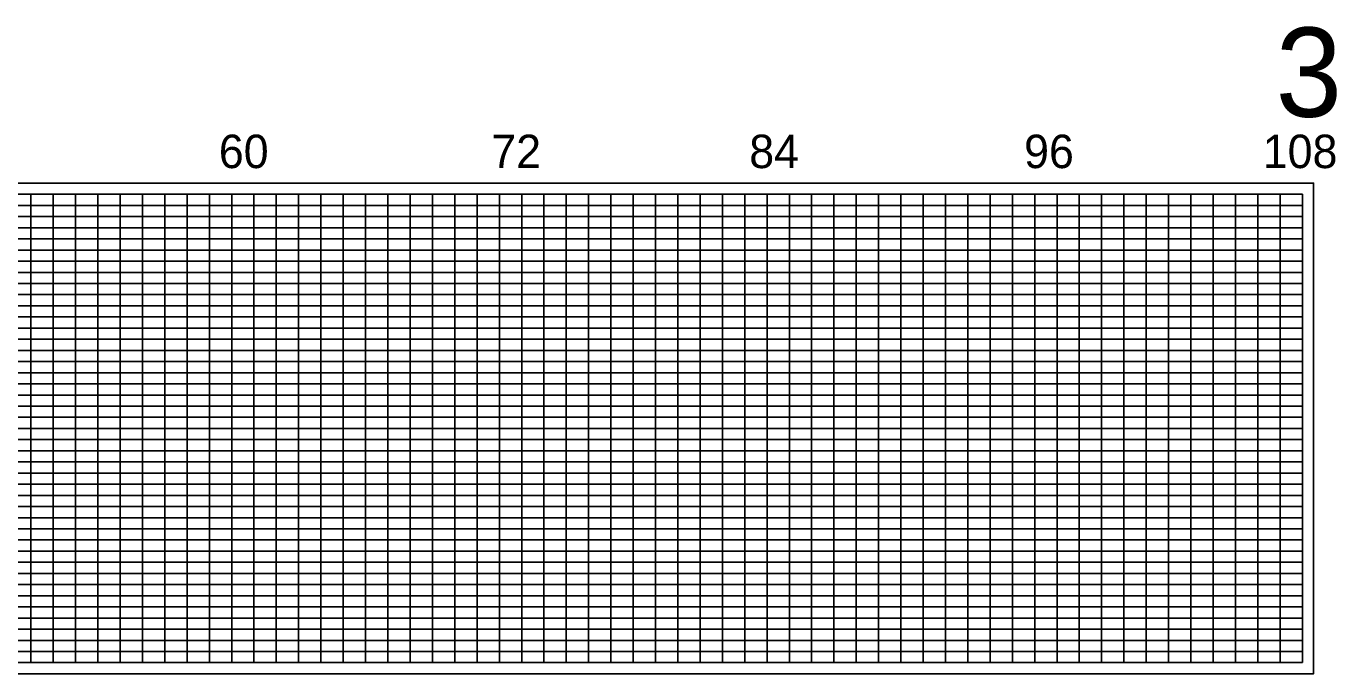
# Model space of a CAD drawing. Extents: x 1894907 to 1905782, y 740939 to 777025.
# Drawn here: x 1898121 to 1901059, y 773439 to 774891 of the extents above; entities that cross this region are included whole.
import ezdxf

# ---------------------------------------------------------------- set-up
doc = ezdxf.new("R2010")
doc.units = 0
for name, color, linetype in [('RD_PD_WallFill', 7, 'Continuous'), ('RD_SHT_IplotShp', 7, 'Continuous'), ('RD_Sketch8', 7, 'Continuous')]:
    doc.layers.add(name, color=color, linetype=linetype)

msp = doc.modelspace()

# ---------------------------------------------------------------- linework, layer by layer
at = {"layer": 'RD_PD_WallFill'}
for p, q in [((1895631.6, 774514.1), (1900981.6, 774514.2)), ((1896081.6, 774489.1), (1900981.6, 774489.1)), ((1898131.6, 773464.2), (1898131.6, 774514.2)), ((1898181.6, 773464.2), (1898181.6, 774514.2)), ((1898231.6, 773464.2), (1898231.6, 774514.2)), ((1898281.6, 773464.2), (1898281.6, 774514.2)), ((1898331.6, 773464.2), (1898331.6, 774514.2)), ((1898381.6, 773464.2), (1898381.6, 774514.2)), ((1898431.6, 773464.2), (1898431.6, 774514.2)), ((1898481.6, 773464.2), (1898481.6, 774514.2)), ((1898531.6, 773464.2), (1898531.6, 774514.2)), ((1898581.6, 773464.2), (1898581.6, 774514.2)), ((1898631.6, 773464.2), (1898631.6, 774514.2)), ((1898681.6, 773464.2), (1898681.6, 774514.2)), ((1898731.6, 773464.1), (1898731.6, 774514.2)), ((1898781.6, 773464.2), (1898781.6, 774514.2)), ((1898831.6, 773464.2), (1898831.6, 774514.2)), ((1898881.6, 773464.2), (1898881.6, 774514.2)), ((1898931.6, 773464.2), (1898931.6, 774514.2)), ((1898981.6, 773464.2), (1898981.6, 774514.2)), ((1899031.6, 773464.1), (1899031.6, 774514.2)), ((1899081.6, 773464.1), (1899081.6, 774514.2)), ((1899131.6, 773464.2), (1899131.6, 774514.2)), ((1899181.6, 773464.2), (1899181.6, 774514.2)), ((1899231.6, 773464.2), (1899231.6, 774514.2)), ((1899281.6, 773464.2), (1899281.6, 774514.2)), ((1899331.6, 773464.2), (1899331.6, 774514.2)), ((1899381.6, 773464.2), (1899381.6, 774514.2)), ((1899431.6, 773464.2), (1899431.6, 774514.2)), ((1899481.6, 773464.2), (1899481.6, 774514.2)), ((1899531.6, 773464.2), (1899531.6, 774514.2)), ((1899581.6, 773464.2), (1899581.6, 774514.2)), ((1899631.6, 773464.2), (1899631.6, 774514.2)), ((1899681.6, 773464.2), (1899681.6, 774514.2)), ((1899731.6, 773464.2), (1899731.6, 774514.2)), ((1899781.6, 773464.2), (1899781.6, 774514.2)), ((1899831.6, 773464.2), (1899831.6, 774514.2)), ((1899881.6, 773464.2), (1899881.6, 774514.2)), ((1899931.6, 773464.2), (1899931.6, 774514.2)), ((1899981.6, 773464.2), (1899981.6, 774514.2)), ((1900031.6, 773464.2), (1900031.6, 774514.2)), ((1900081.6, 773464.2), (1900081.6, 774514.2)), ((1900131.6, 773464.2), (1900131.6, 774514.2)), ((1900181.6, 773464.2), (1900181.6, 774514.2)), ((1900231.6, 773464.2), (1900231.6, 774514.2)), ((1900281.6, 773464.2), (1900281.6, 774514.2)), ((1900331.6, 773464.2), (1900331.6, 774514.2)), ((1900381.6, 773464.2), (1900381.6, 774514.2)), ((1900431.6, 773464.2), (1900431.6, 774514.2)), ((1900481.6, 773464.2), (1900481.6, 774514.2)), ((1900531.6, 773464.2), (1900531.6, 774514.2)), ((1900581.6, 773464.2), (1900581.6, 774514.2)), ((1900631.6, 773464.2), (1900631.6, 774514.2)), ((1900681.6, 773464.2), (1900681.6, 774514.2)), ((1900731.6, 773464.2), (1900731.6, 774514.2)), ((1900781.7, 773464.2), (1900781.6, 774514.2)), ((1900831.6, 773464.2), (1900831.7, 774514.2)), ((1900881.6, 773464.2), (1900881.6, 774514.2)), ((1900931.6, 773464.2), (1900931.6, 774514.2)), ((1900981.7, 773464.2), (1900981.6, 774514.2)), ((1896081.6, 774464.1), (1900981.6, 774464.1)), ((1896081.6, 774439.1), (1900981.6, 774439.1)), ((1896081.6, 774414.2), (1900981.6, 774414.1)), ((1896081.6, 774389.1), (1900981.6, 774389.2)), ((1895631.6, 774364.1), (1900981.6, 774364.1)), ((1895631.6, 774339.1), (1900981.6, 774339.1)), ((1895631.6, 774314.1), (1900981.6, 774314.2)), ((1895631.6, 774289.2), (1900981.6, 774289.1)), ((1895631.6, 774264.2), (1900981.6, 774264.2)), ((1895631.6, 774239.1), (1900981.6, 774239.1)), ((1895631.6, 774214.1), (1900981.6, 774214.1)), ((1895631.6, 774189.2), (1900981.6, 774189.1)), ((1895631.6, 774164.1), (1900981.6, 774164.1)), ((1895631.6, 774139.2), (1900981.6, 774139.1)), ((1895631.6, 774114.1), (1900981.6, 774114.1)), ((1895631.6, 774089.1), (1900981.6, 774089.2)), ((1895631.6, 774064.1), (1900981.6, 774064.1)), ((1895631.6, 774039.1), (1900981.6, 774039.2)), ((1895631.6, 774014.1), (1900981.6, 774014.1)), ((1895631.6, 773989.1), (1900981.6, 773989.1)), ((1895631.6, 773964.2), (1900981.6, 773964.1)), ((1895631.6, 773939.1), (1900981.6, 773939.1)), ((1895631.6, 773914.1), (1900981.6, 773914.1)), ((1895631.6, 773889.1), (1900981.6, 773889.1)), ((1895631.6, 773864.1), (1900981.6, 773864.2)), ((1895631.6, 773839.1), (1900981.6, 773839.1)), ((1895631.6, 773814.1), (1900981.6, 773814.1)), ((1895631.6, 773789.1), (1900981.6, 773789.1)), ((1895631.6, 773764.1), (1900981.6, 773764.1)), ((1895631.6, 773739.1), (1900981.6, 773739.1)), ((1895631.6, 773714.1), (1900981.6, 773714.1)), ((1895631.6, 773689.1), (1900981.6, 773689.1)), ((1895631.6, 773664.1), (1900981.6, 773664.1)), ((1895631.6, 773639.1), (1900981.6, 773639.1)), ((1895631.6, 773614.1), (1900981.6, 773614.1)), ((1895631.6, 773589.1), (1900981.6, 773589.1)), ((1895631.6, 773564.1), (1900981.6, 773564.1)), ((1895631.6, 773539.1), (1900981.6, 773539.1)), ((1895631.6, 773514.1), (1900981.6, 773514.1)), ((1895631.6, 773464.1), (1900981.6, 773464.1)), ((1895681.6, 773489.1), (1900981.6, 773489.1))]:
    msp.add_line(p, q, dxfattribs=at)
at = {"layer": 'RD_SHT_IplotShp'}
msp.add_lwpolyline([(1895606.6, 773439.1), (1901006.6, 773439.1), (1901006.6, 774539.1), (1895606.6, 774539.1)], close=True, dxfattribs=at)

# ---------------------------------------------------------------- texts
at = {"layer": 'RD_PD_WallFill'}
for s, p in [('60', (1898552.8, 774572.8)), ('72', (1899163.5, 774572.8)), ('84', (1899741.7, 774572.8)), ('96', (1900357.8, 774572.8)), ('108', (1900892.8, 774572.8))]:
    msp.add_text(s, height=75, dxfattribs=at).set_placement(p)
at = {"layer": 'RD_Sketch8'}
msp.add_text('3', height=200, dxfattribs=at).set_placement((1900921.7, 774687.9))

doc.saveas('drawing.dxf')
